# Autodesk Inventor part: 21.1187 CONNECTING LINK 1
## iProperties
Created: 2007-07
Part Number: 21.1187 CONNECTING LINK 1
Document SubType Name: Modeling
Designer: Andy Moles
Material: Steel
Mass: 7.01298 g
Surface Area: 16.248 cm^2
Volume: 0.893373 cm^3
Density: 7.85 g/cm^3
Author: Andy Moles
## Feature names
1. Extrusion1
2. Extrusion2
3. Extrusion3
4. Mirror1
